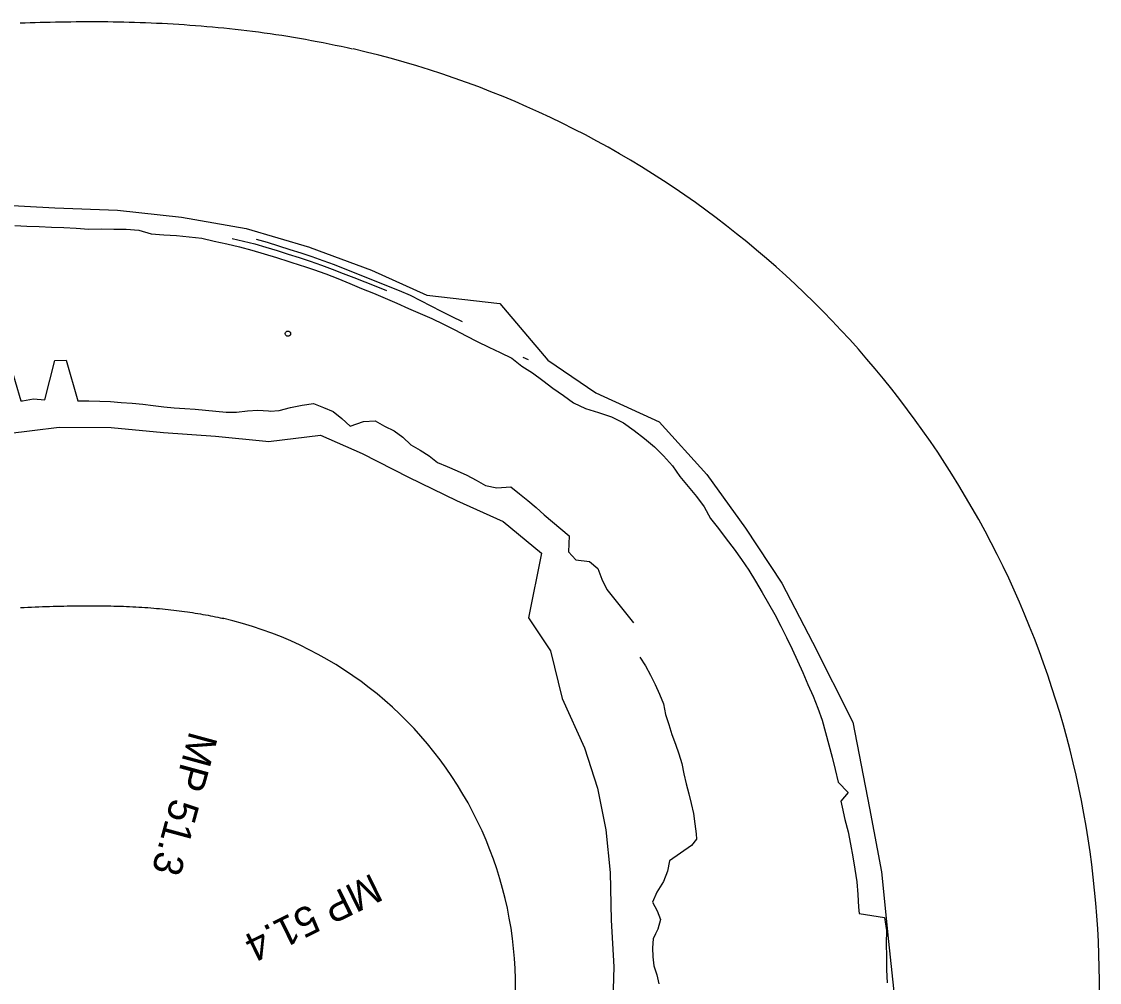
# Model space of a CAD drawing. Extents: x 7860037 to 7875910, y 598622 to 603049.
# Drawn here: x 7871323 to 7872246, y 602184 to 603006 of the extents above; entities that cross this region are included whole.
import ezdxf

# ---------------------------------------------------------------- set-up
doc = ezdxf.new("R2010")
doc.units = 0
for name, color, linetype in [('Level 11', 7, 'Continuous'), ('Level 15', 7, 'Continuous'), ('Level 16', 7, 'Continuous'), ('Level 24', 7, 'Continuous'), ('P_RW_EASE_Perm', 7, 'Continuous')]:
    doc.layers.add(name, color=color, linetype=linetype)

msp = doc.modelspace()

# ---------------------------------------------------------------- linework, layer by layer
at = {"layer": 'Level 11'}
msp.add_circle((7871551.04, 602738.99), 2.25, dxfattribs=at)
at = {"layer": 'Level 16'}
for points in [[(7871317.08, 602831.58), (7871327.58, 602831.03), (7871338.11, 602830.64), (7871348.66, 602830.19), (7871359.24, 602829.87), (7871369.84, 602829.15), (7871380.48, 602828.47), (7871391.14, 602828.67), (7871401.84, 602828.51), (7871412.57, 602828.29), (7871423.33, 602827.66), (7871433.98, 602824.3), (7871444.76, 602823.67), (7871455.58, 602822.89), (7871466.41, 602821.94), (7871477.25, 602820.64), (7871487.99, 602818.3), (7871498.71, 602815.76), (7871509.43, 602813.2), (7871520.12, 602810.45), (7871530.77, 602807.44), (7871541.36, 602804.16), (7871551.89, 602800.66), (7871562.47, 602797.41), (7871564.31, 602796.82), (7871572.96, 602793.87), (7871583.37, 602790.11), (7871593.68, 602786.15), (7871603.9, 602782.01), (7871614.05, 602777.75), (7871624.23, 602773.68), (7871634.32, 602769.45), (7871644.34, 602765.07), (7871654.28, 602760.55), (7871664.28, 602756.2), (7871674.29, 602751.91), (7871684.14, 602747.24), (7871693.86, 602742.33), (7871703.49, 602737.25), (7871713.13, 602732.22), (7871722.98, 602727.55), (7871732.77, 602722.73), (7871742.64, 602718), (7871751.31, 602711.27), (7871760.45, 602705.34), (7871769.26, 602698.94), (7871777.95, 602692.37), (7871786.85, 602686.13), (7871795.62, 602679.7), (7871805.74, 602675), (7871816.86, 602671.43), (7871828.16, 602667.84), (7871838.41, 602662.79), (7871847.35, 602656.12), (7871856.23, 602649.34), (7871864.81, 602642.19), (7871872.71, 602634.31), (7871880.15, 602625.99), (7871886.66, 602616.82), (7871893.74, 602608.24), (7871900.74, 602599.61), (7871907.42, 602590.73), (7871912.86, 602580.87), (7871919.66, 602572.17), (7871926.37, 602563.41), (7871933.04, 602554.61), (7871939.44, 602545.61), (7871945.63, 602536.47), (7871951.38, 602527.04), (7871957.04, 602517.57), (7871962.59, 602508.05), (7871968.04, 602498.47), (7871973.16, 602488.71), (7871977.99, 602478.81), (7871982.71, 602468.87), (7871987.31, 602458.89), (7871991.8, 602448.86), (7871996.17, 602438.79), (7872000.68, 602428.78), (7872004.66, 602418.55), (7872008.51, 602408.28), (7872011.43, 602397.67), (7872014.16, 602387.02), (7872016.86, 602376.41), (7872019.5, 602365.8), (7872022.02, 602355.17)], [(7871503.22, 602820.31), (7871513.01, 602818.28), (7871522.64, 602815.88), (7871532.25, 602813.12), (7871541.71, 602810.13), (7871551.23, 602807.09), (7871560.76, 602804.05), (7871570.2, 602800.97), (7871579.64, 602797.67), (7871588.96, 602794.27), (7871598.26, 602790.6), (7871607.56, 602786.92), (7871616.86, 602783.23), (7871626.15, 602779.53), (7871635.43, 602775.83)], [(7871523.74, 602819.89), (7871533.39, 602817.29), (7871543, 602814.2), (7871552.52, 602811.16), (7871562.05, 602808.12), (7871571.6, 602804.93), (7871581.04, 602801.63), (7871590.49, 602798.14), (7871599.79, 602794.47), (7871609.09, 602790.78), (7871618.38, 602787.08), (7871627.67, 602783.39), (7871636.97, 602779.71), (7871646.26, 602776.02)], [(7871646.26, 602776.02), (7871655.57, 602771.9), (7871664.55, 602767.49), (7871673.4, 602762.84), (7871682.27, 602758.21)], [(7871682.27, 602758.21), (7871691.22, 602753.75), (7871700.15, 602749.26)], [(7871312.56, 602714.64), (7871322.32, 602681.48), (7871323.84, 602681.41), (7871333.32, 602683.3), (7871342.89, 602682.23), (7871351.52, 602716.06)], [(7871351.52, 602716.06), (7871361.21, 602716.31)], [(7871361.21, 602716.31), (7871371.21, 602681.53), (7871380.57, 602681.35), (7871389.88, 602681.17), (7871399.16, 602680.85), (7871408.38, 602680.12), (7871417.56, 602679.51), (7871426.67, 602678.54), (7871435.73, 602677.45), (7871444.73, 602676.27), (7871453.73, 602675.58), (7871462.7, 602675.04), (7871471.63, 602674.38), (7871480.51, 602673.59), (7871489.35, 602672.68), (7871498.16, 602671.76), (7871507.12, 602671.87), (7871516.3, 602673.02), (7871525.38, 602673.43), (7871534.28, 602672.86), (7871535.81, 602672.63), (7871543.45, 602673.24), (7871553.27, 602675.78), (7871563.09, 602677.69), (7871572.97, 602679.21), (7871581.44, 602675.89), (7871589.84, 602672.38), (7871597.3, 602666.34), (7871604.43, 602659.73), (7871615.73, 602663.91), (7871625.78, 602664.4), (7871633.76, 602659.79), (7871642.04, 602655.93), (7871649.52, 602650.41), (7871656.39, 602643.81), (7871664.26, 602639.33), (7871671.83, 602634.32), (7871679.07, 602628.78), (7871687.45, 602625.24), (7871695.86, 602621.67), (7871704.12, 602617.78), (7871712.22, 602613.56), (7871720.1, 602608.98), (7871729.97, 602607.12), (7871741.95, 602607.83)], [(7871752.18, 602718.89), (7871756.75, 602716.86)], [(7871741.95, 602607.83), (7871749.18, 602601.97), (7871756.42, 602596.12), (7871763.47, 602590.06), (7871770.52, 602583.99), (7871777.57, 602577.93), (7871784.63, 602571.87), (7871791.7, 602565.81)], [(7871791.7, 602565.81), (7871791.38, 602552.27), (7871797.49, 602545.47), (7871809.16, 602543.91), (7871816.33, 602537.93)], [(7871816.33, 602537.93), (7871819.93, 602528.74), (7871823.97, 602520.09), (7871829.69, 602512.92), (7871835.42, 602505.76), (7871841.16, 602498.61), (7871846.9, 602491.45)], [(7871852.4, 602462.15), (7871857.12, 602454.53), (7871861.54, 602446.73), (7871865.52, 602438.69), (7871869.14, 602430.46), (7871872.45, 602422.11), (7871874.21, 602412.99), (7871877.07, 602404.52), (7871879.7, 602395.99), (7871882.82, 602387.73), (7871885.79, 602379.43), (7871888.24, 602370.92), (7871890.11, 602362.24), (7871892.11, 602353.65), (7871894.18, 602345.13), (7871896.37, 602336.68), (7871898.35, 602328.18), (7871899.53, 602319.47), (7871900.45, 602310.74), (7871900.83, 602306.38), (7871896.54, 602300.84), (7871877.75, 602287.65), (7871876.13, 602278.95), (7871872.45, 602269.97), (7871866.87, 602260.83), (7871863.28, 602252.27), (7871867.09, 602244.95), (7871870.13, 602237.44), (7871867.67, 602229.26), (7871865.87, 602225.15), (7871863.88, 602221.07), (7871863.13, 602213.26), (7871863.57, 602205.57), (7871864.39, 602197.89), (7871866.88, 602190.23), (7871868.68, 602182.49)], [(7872022.02, 602355.17), (7872030.67, 602346.24), (7872024.42, 602338.91)], [(7872024.42, 602338.91), (7872025.51, 602333.59), (7872027.97, 602323.02), (7872030.74, 602312.52), (7872032.82, 602301.87), (7872034.68, 602291.17), (7872036.46, 602280.47), (7872038.22, 602269.76), (7872038.86, 602258.9), (7872039.5, 602248.07), (7872040.11, 602242.69)], [(7872040.11, 602242.69), (7872061.67, 602239.24), (7872063.45, 602228.14), (7872063.34, 602216.91), (7872063.55, 602205.71), (7872063.4, 602194.52), (7872064.14, 602183.34)]]:
    msp.add_lwpolyline(points, dxfattribs=at)
at = {"layer": 'Level 24'}
for points in [[(7870847.31, 602784.87), (7870909.33, 602789.03), (7870932.79, 602858.75), (7870971.55, 602853.14), (7871021.37, 602856.32), (7871097.29, 602858.03), (7871101.2, 602858.62), (7871135.05, 602853.24), (7871194.75, 602854.97), (7871195.63, 602855.01), (7871247.36, 602852.34), (7871286.31, 602850.23), (7871299.24, 602849.41), (7871351.39, 602846.62), (7871404.98, 602844.76), (7871459.93, 602838.83), (7871515.33, 602828.97), (7871569.41, 602813.11), (7871570.17, 602812.87), (7871622.63, 602793.28), (7871670.04, 602771.92)], [(7871670.04, 602771.92), (7871732.49, 602764.69), (7871773.55, 602716.37)], [(7871773.55, 602716.37), (7871814.64, 602688.29), (7871868.81, 602663.64), (7871909.57, 602618.54), (7871942.76, 602572.4), (7871973.94, 602525.33), (7872000.08, 602475.01), (7872034.72, 602406.48)], [(7871209.32, 602656.63), (7871256.41, 602657.71), (7871294.21, 602651.89), (7871308.86, 602653.33), (7871355.19, 602658.98), (7871399.67, 602658.74), (7871444.42, 602654.51), (7871488.91, 602651.14), (7871532.21, 602647.02), (7871534.44, 602646.74), (7871579, 602652.24), (7871614.63, 602636.47), (7871654.21, 602616.07), (7871695.27, 602596.26), (7871735.32, 602578.18), (7871768.24, 602551.12), (7871756.9, 602495.72)], [(7871756.9, 602495.72), (7871775.78, 602467.55), (7871785.96, 602426.75), (7871805.04, 602384.36), (7871816.04, 602349.85), (7871823.34, 602314.32), (7871827.02, 602277.84), (7871827.79, 602236.82), (7871830.15, 602196.97), (7871828.92, 602158.86)], [(7872034.72, 602406.48), (7872049, 602332.69), (7872059.11, 602278.36), (7872065.36, 602218.66), (7872074.65, 602130.17), (7872107.83, 602109.76), (7872138.75, 602091.68), (7872137.49, 602024.78), (7872123.41, 601957.42), (7872104.25, 601901.03), (7872096.92, 601887.57), (7872068.7, 601837.47), (7872040.49, 601787.1), (7872008.24, 601738.07), (7871974.66, 601693.67), (7871943.06, 601654), (7871913.07, 601613.46), (7871880.61, 601573.61), (7871850.35, 601535.88), (7871822.92, 601500.58), (7871799.71, 601464.99), (7871769.59, 601413.57), (7871741.9, 601394.08)]]:
    msp.add_lwpolyline(points, dxfattribs=at)
at = {"layer": 'P_RW_EASE_Perm'}
for points in [[(7871321.64, 603004.94), (7871325.92, 603005.1), (7871330.22, 603005.25), (7871334.54, 603005.39), (7871338.87, 603005.52), (7871343.22, 603005.63), (7871347.59, 603005.74), (7871351.98, 603005.84), (7871356.38, 603005.92), (7871360.8, 603005.99), (7871365.23, 603006.04), (7871369.69, 603006.09), (7871374.16, 603006.12), (7871378.65, 603006.13), (7871383.15, 603006.13), (7871387.67, 603006.12), (7871392.21, 603006.09), (7871396.77, 603006.05), (7871401.34, 603005.98), (7871405.93, 603005.91), (7871410.53, 603005.81), (7871415.16, 603005.7), (7871419.8, 603005.57), (7871424.45, 603005.42), (7871429.12, 603005.25), (7871433.81, 603005.06), (7871438.51, 603004.86), (7871443.23, 603004.63), (7871447.97, 603004.38), (7871452.72, 603004.11), (7871457.48, 603003.82), (7871462.27, 603003.51), (7871467.06, 603003.17), (7871471.88, 603002.81), (7871476.71, 603002.43), (7871481.55, 603002.02), (7871486.41, 603001.59), (7871491.28, 603001.14), (7871496.17, 603000.66), (7871501.07, 603000.15), (7871505.99, 602999.62), (7871510.92, 602999.06), (7871515.86, 602998.47), (7871520.82, 602997.86), (7871525.79, 602997.21), (7871530.77, 602996.54), (7871535.77, 602995.84), (7871540.78, 602995.11), (7871545.8, 602994.35), (7871550.84, 602993.55), (7871555.89, 602992.73), (7871560.94, 602991.87), (7871566.02, 602990.99), (7871571.1, 602990.06), (7871576.19, 602989.11), (7871581.29, 602988.12), (7871586.41, 602987.1), (7871591.53, 602986.04), (7871596.67, 602984.95), (7871601.81, 602983.82), (7871606.18, 602982.83)], [(7871321.98, 602504.46), (7871325.16, 602504.62), (7871328.33, 602504.77), (7871331.48, 602504.92), (7871334.61, 602505.06), (7871337.72, 602505.19), (7871340.82, 602505.31), (7871343.9, 602505.42), (7871346.97, 602505.53), (7871350.01, 602505.63), (7871353.05, 602505.72), (7871356.06, 602505.8), (7871359.06, 602505.87), (7871362.04, 602505.94), (7871365, 602505.99), (7871367.95, 602506.04), (7871370.88, 602506.08), (7871373.8, 602506.1), (7871376.69, 602506.12), (7871379.57, 602506.13), (7871382.44, 602506.13), (7871385.28, 602506.13), (7871388.11, 602506.11), (7871390.93, 602506.08), (7871393.72, 602506.04), (7871396.5, 602505.99), (7871399.26, 602505.94), (7871402.01, 602505.87), (7871404.73, 602505.79), (7871407.44, 602505.71), (7871410.14, 602505.61), (7871412.81, 602505.5), (7871415.47, 602505.39), (7871418.11, 602505.26), (7871420.73, 602505.12), (7871423.34, 602504.97), (7871425.93, 602504.82), (7871428.5, 602504.65), (7871431.05, 602504.47), (7871433.58, 602504.28), (7871436.1, 602504.08), (7871438.6, 602503.87), (7871441.08, 602503.65), (7871443.55, 602503.42), (7871445.99, 602503.18), (7871448.42, 602502.93), (7871450.83, 602502.67), (7871453.22, 602502.4), (7871455.59, 602502.11), (7871457.95, 602501.82), (7871460.28, 602501.52), (7871462.6, 602501.21), (7871464.9, 602500.88), (7871467.18, 602500.55), (7871469.44, 602500.21), (7871471.69, 602499.86), (7871473.91, 602499.49), (7871476.12, 602499.12), (7871478.31, 602498.74), (7871480.47, 602498.34), (7871482.62, 602497.94), (7871484.75, 602497.53), (7871486.86, 602497.11), (7871488.96, 602496.67), (7871491.03, 602496.23), (7871493.08, 602495.78), (7871495.9, 602495.15)]]:
    msp.add_lwpolyline(points, dxfattribs=at)
for radius in [822.96, 322.96]:
    msp.add_arc((7871422.88, 602180.55), radius, 337.83856, 77.07443, dxfattribs=at)

# ---------------------------------------------------------------- texts
at = {"layer": 'Level 15'}
for s, rotation, p in [('MP 51.3', 254.78574, (7871466.98, 602399.6)), ('MP 51.4', 206.0906, (7871623.2, 602277.49))]:
    msp.add_text(s, height=25, rotation=rotation, dxfattribs=at).set_placement(p)

doc.saveas('drawing.dxf')
